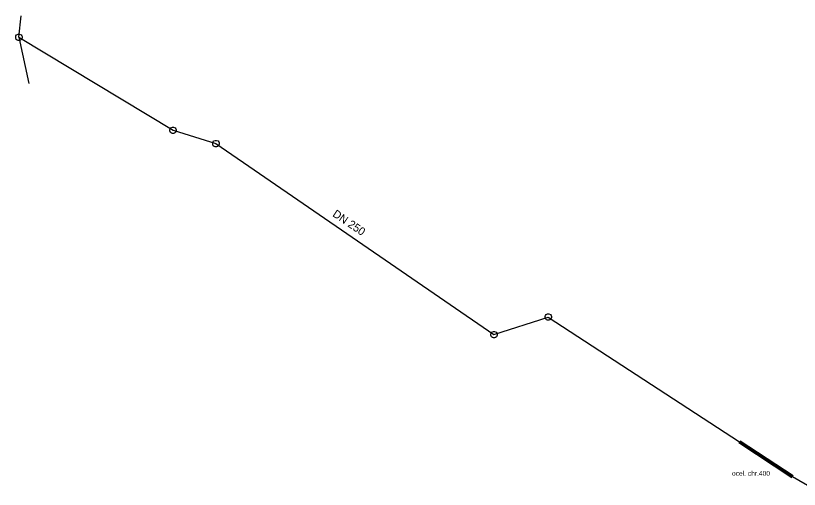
# Model space of a CAD drawing. Extents: x -717256 to -716843, y -1145423 to -1142840.
# Drawn here: x -717108.4 to -716986, y -1145391.3 to -1145317.4 of the extents above; entities that cross this region are included whole.
import ezdxf

# ---------------------------------------------------------------- set-up
doc = ezdxf.new("R2010")
doc.units = 0
doc.layers.add('Vrstva 29', color=7, linetype='Continuous')
doc.layers.add('Vrstva 30', color=7, linetype='Continuous')

msp = doc.modelspace()

# ---------------------------------------------------------------- linework, layer by layer
at = {"layer": 'Vrstva 29'}
for p, q in [((-716987.228, -1145389.497), (-716995.502, -1145384.067)), ((-716995.282, -1145383.732), (-716987.008, -1145389.162))]:
    msp.add_line(p, q, dxfattribs=at)
at = {"layer": 'Vrstva 30'}
for p, q in [((-717107.924, -1145320.737), (-717107.575, -1145317.363)), ((-717108.424, -1145320.637), (-717108.374, -1145320.487)), ((-717108.424, -1145320.837), (-717108.424, -1145320.637)), ((-717108.324, -1145321.087), (-717108.424, -1145320.837)), ((-717108.374, -1145320.487), (-717108.274, -1145320.337)), ((-717108.174, -1145321.187), (-717108.324, -1145321.087)), ((-717108.274, -1145320.337), (-717108.024, -1145320.237)), ((-717108.024, -1145321.237), (-717108.174, -1145321.187)), ((-717108.024, -1145320.237), (-717107.824, -1145320.237)), ((-717107.824, -1145321.237), (-717108.024, -1145321.237)), ((-717107.924, -1145320.737), (-717083.851, -1145335.257)), ((-717107.924, -1145320.737), (-717106.355, -1145327.955)), ((-717107.824, -1145320.237), (-717107.574, -1145320.337)), ((-717107.674, -1145321.187), (-717107.824, -1145321.237)), ((-717107.524, -1145321.087), (-717107.674, -1145321.187)), ((-717107.574, -1145320.337), (-717107.474, -1145320.487)), ((-717107.424, -1145320.837), (-717107.524, -1145321.087)), ((-717107.474, -1145320.487), (-717107.424, -1145320.637)), ((-717107.424, -1145320.637), (-717107.424, -1145320.837)), ((-717084.201, -1145334.857), (-717083.951, -1145334.757)), ((-717083.951, -1145334.757), (-717083.751, -1145334.757)), ((-717083.751, -1145334.757), (-717083.501, -1145334.857)), ((-717084.351, -1145335.157), (-717084.301, -1145335.007)), ((-717084.351, -1145335.357), (-717084.351, -1145335.157)), ((-717084.251, -1145335.607), (-717084.351, -1145335.357)), ((-717084.301, -1145335.007), (-717084.201, -1145334.857)), ((-717084.101, -1145335.707), (-717084.251, -1145335.607)), ((-717083.951, -1145335.757), (-717084.101, -1145335.707)), ((-717083.751, -1145335.757), (-717083.951, -1145335.757)), ((-717083.851, -1145335.257), (-717077.154, -1145337.324)), ((-717083.601, -1145335.707), (-717083.751, -1145335.757)), ((-717083.451, -1145335.607), (-717083.601, -1145335.707)), ((-717083.501, -1145334.857), (-717083.401, -1145335.007)), ((-717083.351, -1145335.357), (-717083.451, -1145335.607)), ((-717083.401, -1145335.007), (-717083.351, -1145335.157)), ((-717083.351, -1145335.157), (-717083.351, -1145335.357)), ((-717077.654, -1145337.224), (-717077.604, -1145337.074)), ((-717077.604, -1145337.074), (-717077.504, -1145336.924)), ((-717077.504, -1145336.924), (-717077.254, -1145336.824)), ((-717077.254, -1145336.824), (-717077.054, -1145336.824)), ((-717077.054, -1145336.824), (-717076.804, -1145336.924)), ((-717076.804, -1145336.924), (-717076.704, -1145337.074)), ((-717076.704, -1145337.074), (-717076.654, -1145337.224)), ((-717077.654, -1145337.424), (-717077.654, -1145337.224)), ((-717077.554, -1145337.674), (-717077.654, -1145337.424)), ((-717077.404, -1145337.774), (-717077.554, -1145337.674)), ((-717077.254, -1145337.824), (-717077.404, -1145337.774)), ((-717077.054, -1145337.824), (-717077.254, -1145337.824)), ((-717077.154, -1145337.324), (-717033.719, -1145367.149)), ((-717076.904, -1145337.774), (-717077.054, -1145337.824)), ((-717076.754, -1145337.674), (-717076.904, -1145337.774)), ((-717076.654, -1145337.424), (-717076.754, -1145337.674)), ((-717076.654, -1145337.224), (-717076.654, -1145337.424)), ((-717025.694, -1145364.154), (-717025.594, -1145364.004)), ((-717025.594, -1145364.004), (-717025.344, -1145363.904)), ((-717025.344, -1145363.904), (-717025.144, -1145363.904)), ((-717025.144, -1145363.904), (-717024.894, -1145364.004)), ((-717024.894, -1145364.004), (-717024.794, -1145364.154)), ((-717033.719, -1145367.149), (-717025.244, -1145364.404)), ((-717025.744, -1145364.304), (-717025.694, -1145364.154)), ((-717025.744, -1145364.504), (-717025.744, -1145364.304)), ((-717025.644, -1145364.754), (-717025.744, -1145364.504)), ((-717025.494, -1145364.854), (-717025.644, -1145364.754)), ((-717025.344, -1145364.904), (-717025.494, -1145364.854)), ((-717025.144, -1145364.904), (-717025.344, -1145364.904)), ((-717025.244, -1145364.404), (-716995.392, -1145383.9)), ((-717024.994, -1145364.854), (-717025.144, -1145364.904)), ((-717024.844, -1145364.754), (-717024.994, -1145364.854)), ((-717024.744, -1145364.504), (-717024.844, -1145364.754)), ((-717024.794, -1145364.154), (-717024.744, -1145364.304)), ((-717024.744, -1145364.304), (-717024.744, -1145364.504)), ((-717034.219, -1145367.049), (-717034.169, -1145366.899)), ((-717034.219, -1145367.249), (-717034.219, -1145367.049)), ((-717034.119, -1145367.499), (-717034.219, -1145367.249)), ((-717034.169, -1145366.899), (-717034.069, -1145366.749)), ((-717033.969, -1145367.599), (-717034.119, -1145367.499)), ((-717034.069, -1145366.749), (-717033.819, -1145366.649)), ((-717033.819, -1145367.649), (-717033.969, -1145367.599)), ((-717033.819, -1145366.649), (-717033.619, -1145366.649)), ((-717033.619, -1145367.649), (-717033.819, -1145367.649)), ((-717033.619, -1145366.649), (-717033.369, -1145366.749)), ((-717033.469, -1145367.599), (-717033.619, -1145367.649)), ((-717033.319, -1145367.499), (-717033.469, -1145367.599)), ((-717033.369, -1145366.749), (-717033.269, -1145366.899)), ((-717033.219, -1145367.249), (-717033.319, -1145367.499)), ((-717033.269, -1145366.899), (-717033.219, -1145367.049)), ((-717033.219, -1145367.049), (-717033.219, -1145367.249)), ((-716987.118, -1145389.33), (-716995.392, -1145383.9)), ((-716983.743, -1145391.3), (-716987.118, -1145389.33))]:
    msp.add_line(p, q, dxfattribs=at)

# ---------------------------------------------------------------- texts
msp.add_text('DN 250', height=1.25, rotation=325.8, dxfattribs=at).set_placement((-717059.043, -1145348.591))
msp.add_text('ocel. chr.400', height=0.74999, dxfattribs=at).set_placement((-716996.544, -1145389.177))

doc.saveas('drawing.dxf')
